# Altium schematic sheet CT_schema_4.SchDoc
size 383 x 311 mm
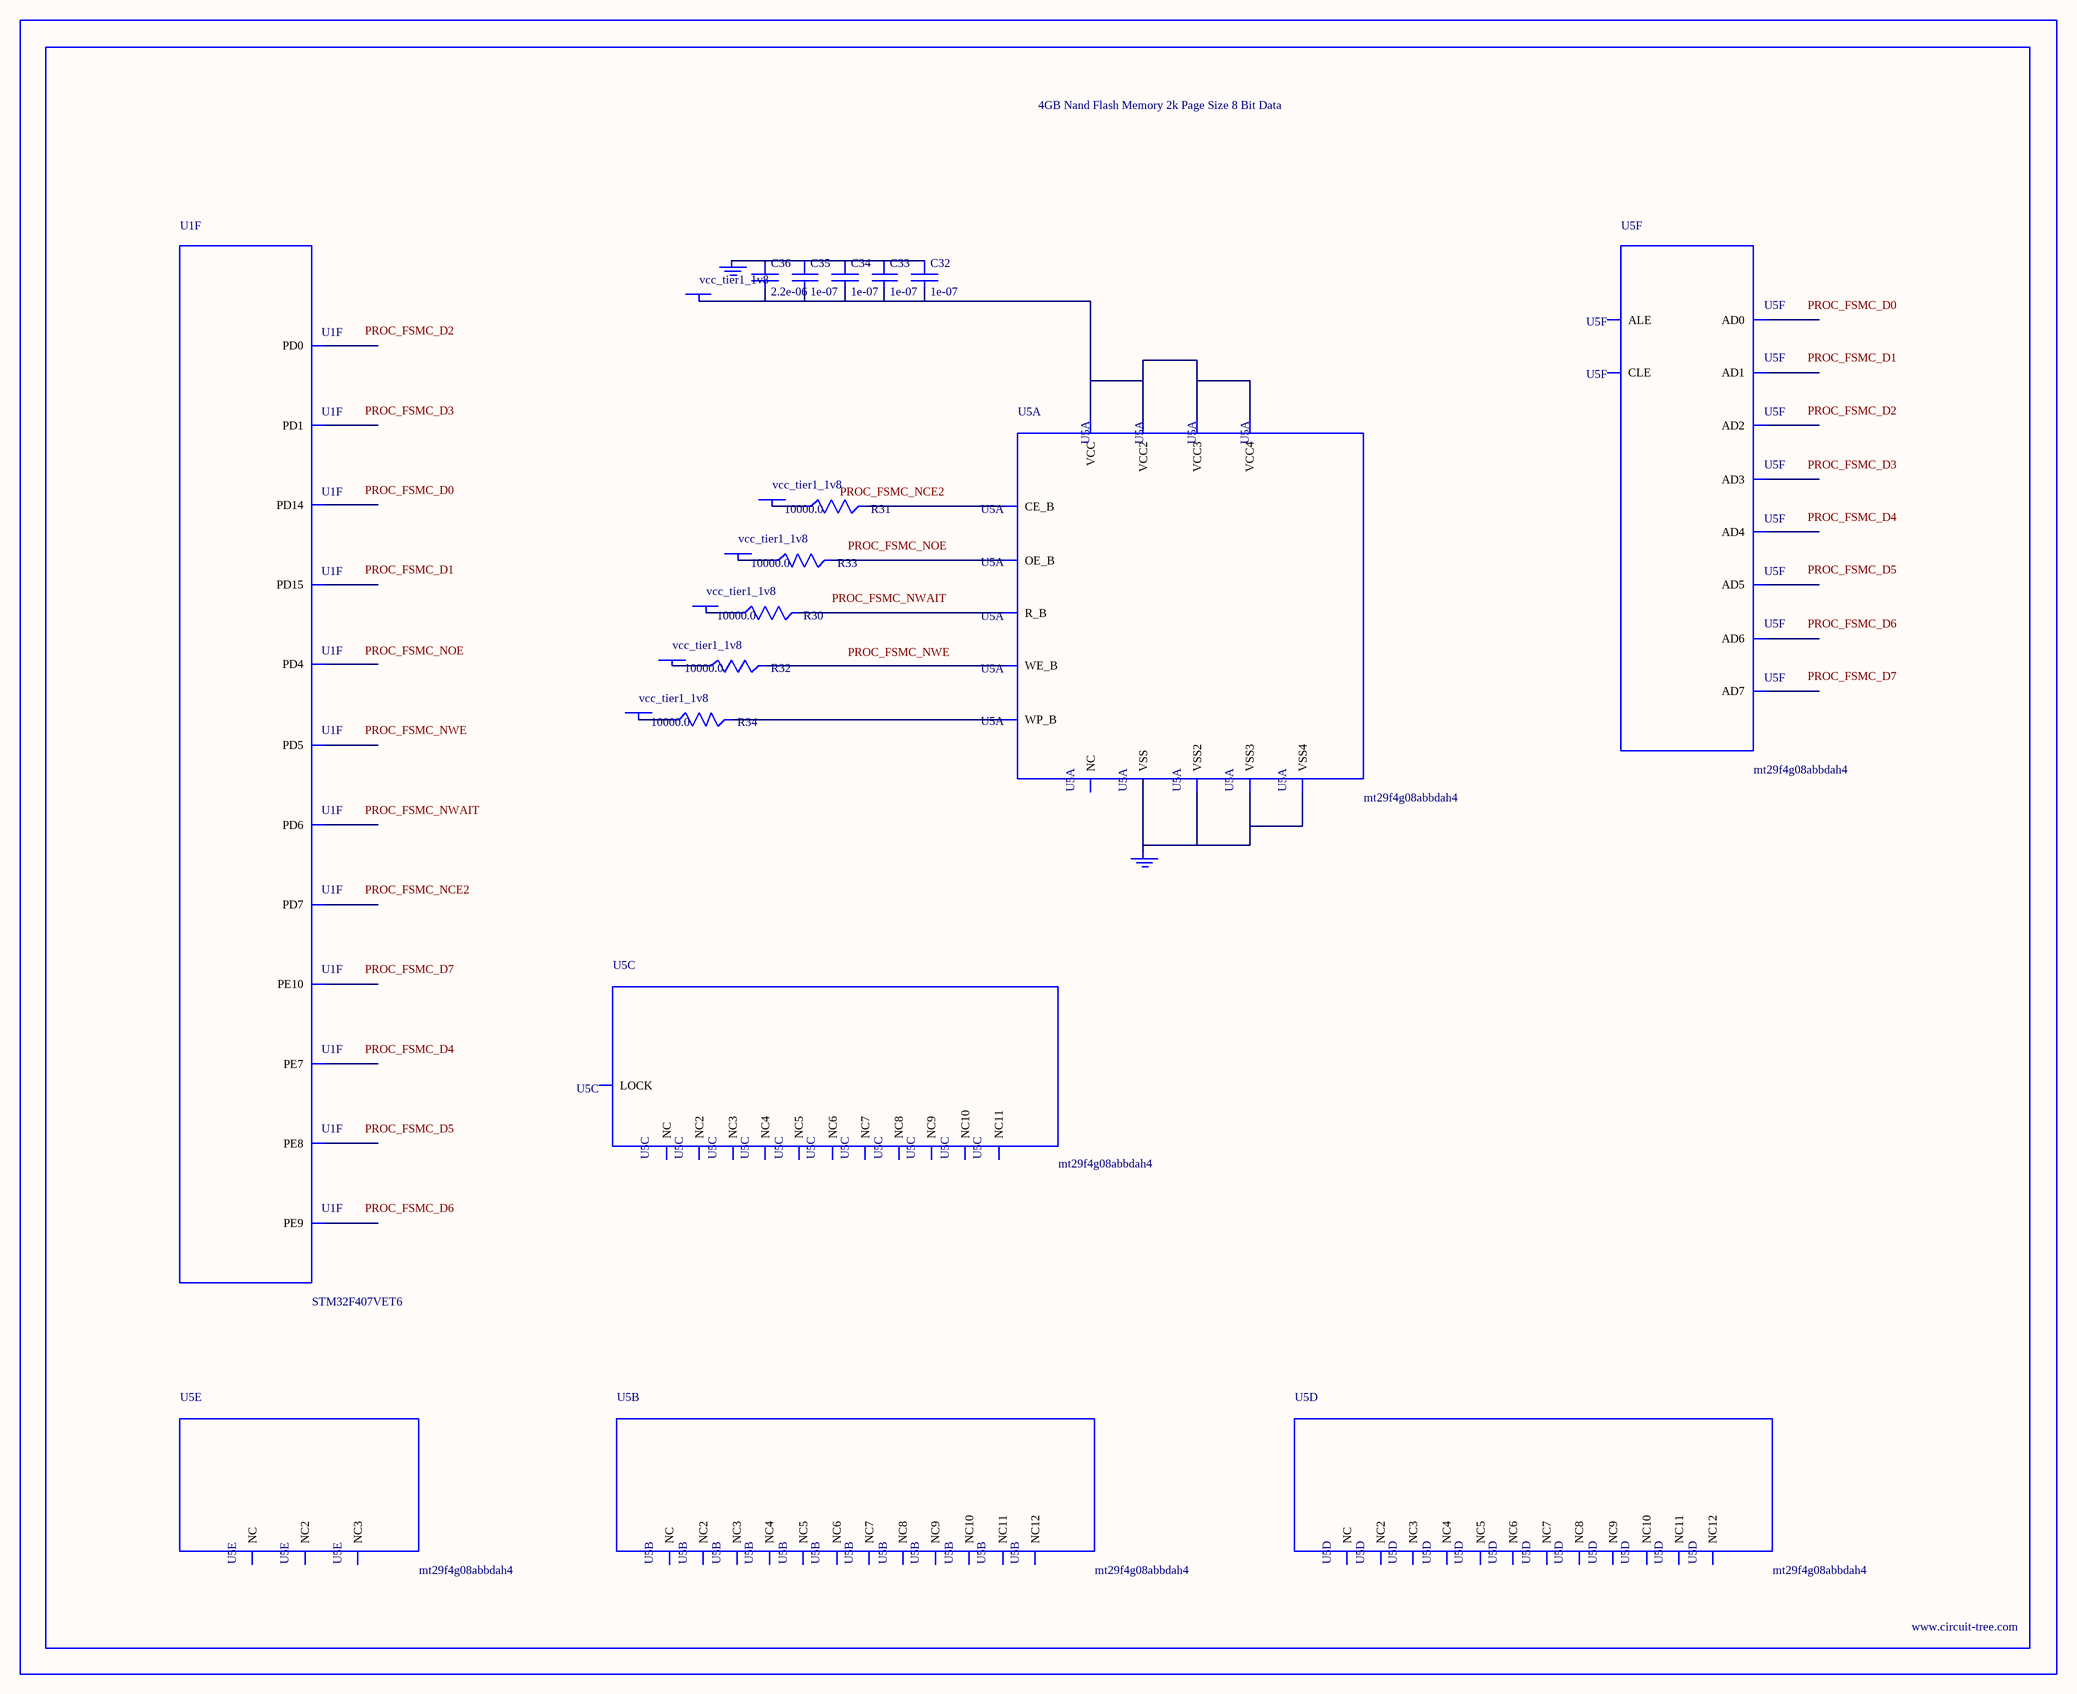
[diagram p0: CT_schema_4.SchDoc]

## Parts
BORDER3  (no value)
C32  1e-07  [C0402]
C33  1e-07  [C0402]
C34  1e-07  [C0402]
C35  1e-07  [C0402]
C36  2.2e-06  [C0603]
GND_INSTANCE_3_0  (no value)
GND_INSTANCE_3_1  (no value)
POWER_INSTANCE_3_0  vcc_tier1_1v8
POWER_INSTANCE_3_1  vcc_tier1_1v8
POWER_INSTANCE_3_2  vcc_tier1_1v8
POWER_INSTANCE_3_3  vcc_tier1_1v8
POWER_INSTANCE_3_4  vcc_tier1_1v8
POWER_INSTANCE_3_5  vcc_tier1_1v8
R30  10000.0  [R0603]
R31  10000.0  [R0603]
R32  10000.0  [R0603]
R33  10000.0  [R0603]
R34  10000.0  [R0603]
U1  STM32F407VET6  [LQFP100]  (part F of 8)
U5  mt29f4g08abbdah4  [VFBGA-63]  (parts A,B,C,D,E,F of 6)

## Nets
NetC32_1: C32.1 C33.1 C34.1 C35.1 C36.1 GND_INSTANCE_3_0.0(GND)
NetC32_2: C32.2 C33.2 C34.2 C35.2 C36.2 POWER_INSTANCE_3_0.0(PWR) U5.D3(VCC) U5.G4(VCC2) U5.H8(VCC3) U5.J6(VCC4)
NetGND_INSTANCE_3_1_0: GND_INSTANCE_3_1.0(GND) U5.C5(VSS) U5.F7(VSS2) U5.K3(VSS3) U5.K8(VSS4)
NetPOWER_INSTANCE_3_1_0: POWER_INSTANCE_3_1.0(PWR) R30.1
NetPOWER_INSTANCE_3_2_0: POWER_INSTANCE_3_2.0(PWR) R31.1
NetPOWER_INSTANCE_3_3_0: POWER_INSTANCE_3_3.0(PWR) R32.1
NetPOWER_INSTANCE_3_4_0: POWER_INSTANCE_3_4.0(PWR) R33.1
NetPOWER_INSTANCE_3_5_0: POWER_INSTANCE_3_5.0(PWR) R34.1
NetR30_2: R30.2 U5.C8(R_B)
NetR31_2: R31.2 U5.C6(CE_B)
NetR32_2: R32.2 U5.C7(WE_B)
NetR33_2: R33.2 U5.D4(OE_B)
NetR34_2: R34.2 U5.C3(WP_B)

Not connected (* = marked no-connect by the designer): U1 38(PE7) 39(PE8) 40(PE9) 41(PE10) 61(PD14) 62(PD15) 81(PD0) 82(PD1) 85(PD4) 86(PD5) 87(PD6) 88(PD7); U5 A1(NC) A2(NC3) A9(NC4) A10(NC2) B1(NC5) B9(NC7) B10(NC6) C4(ALE) D5(CLE) D6(NC8) D7(NC9) D8(NC10) E3(NC11) E4(NC12) E5(NC) E6(NC2) E7(NC3) E8(NC4) F3(NC5) F4(NC6) F5(NC7) F6(NC8) F8(NC9) G3(NC) G5(LOCK) G6(NC10) G7(NC11) G8(NC) H3(NC2) H4(AD0) H5(NC3) H6(NC4) H7(NC5) J3(NC6) J4(AD1) J5(NC7) J7(AD5) J8(AD7) K4(AD2) K5(AD3) K6(AD4) K7(AD6) L1(NC8) L2(NC10) L9(NC11) L10(NC9) M1(NC12) M2(NC2) M9(NC3) M10(NC)

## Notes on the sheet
- Labels drawn without touching a wire or pin: PROC_FSMC_D0, PROC_FSMC_D1, PROC_FSMC_D2, PROC_FSMC_D3, PROC_FSMC_D4, PROC_FSMC_D5, PROC_FSMC_D6, PROC_FSMC_D7, PROC_FSMC_NCE2, PROC_FSMC_NOE, PROC_FSMC_NWAIT, PROC_FSMC_NWE

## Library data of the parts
BORDER3 = BORDER_PAGE3
C32-C35 = C0402C104K3RACTU
C36 = C0603C225K8RACTU
GND_INSTANCE_3_0 GND_INSTANCE_3_1 = GND
POWER_INSTANCE_3_0-POWER_INSTANCE_3_5 = PWR
R30-R34 = RC0603JR-0710KL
